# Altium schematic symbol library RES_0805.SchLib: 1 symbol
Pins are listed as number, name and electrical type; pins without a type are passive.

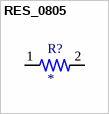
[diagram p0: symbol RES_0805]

## RES_0805
designator R?
1% 0.125W; MP: 1-2176071-4
footprint RES_0805
pins: 1, 2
